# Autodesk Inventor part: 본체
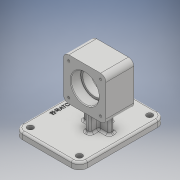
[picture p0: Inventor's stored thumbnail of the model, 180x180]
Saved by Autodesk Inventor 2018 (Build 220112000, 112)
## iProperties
Created: 2020-11
Part Number: 본체
Material: 일반
Document SubType Name: Modeling
Designer: USER
Density: 1 g/cm^3
Appearance: 기본값
Author: USER
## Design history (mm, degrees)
sketch "스케치1"
  geometry: L1 (-49, -65)-(49, -65); L2 (49, -65)-(49, 65); L3 (49, 65)-(-49, 65); L4 (-49, 65)-(-49, -65); L5 (-49, -65)-(49, 65); L6 (49, -65)-(-49, 65); 1 further point
  constraints: 12 end point, 2 midpoint, 2 parallel, 1 horizontal, 1 perpendicular
  dimensions: "d0" = 98 distance of L3.end L2.end; "d1" = 130 distance of L2.end L1.end
extrude "돌출1" new body sketch "스케치1" distance "d2" = 10; taper "d3" = 0 deg
fillet "모깎기1" dims "d4" = 12
fillet "모깎기2" dims "d5" = 3
sketch "스케치2"
  geometry: L1 (19, 38)-(-45, 38); L2 (-45, 38)-(-45, 102); L3 (-45, 102)-(19, 102); L4 (19, 102)-(19, 38); L5 (19, 38)-(-45, 102); L6 (-45, 38)-(19, 102); L7 (-13, 102)-(-13, 38); L8 (49, 7)-(49, 0) reference; L9 (19, 70)-(-45, 70); L10 (37, 0)-(-37, 0) reference; 2 further points
  constraints: 16 end point, 6 midpoint, 2 parallel, 1 horizontal, 1 perpendicular
  dimensions: "d6" = 64 distance of L2.end L3.end; "d7" = 64 distance of L1.end L2.end; "d8" = 62 distance between parallel lines of L8 L7; "d9" = 70 distance between parallel lines of L9 L10
extrude "돌출2" join sketch "스케치2" stored distance "d10" = 42; taper "d11" = 0 deg
fillet "모깎기3" dims "d12" = 8
sketch "스케치3"
  geometry: L1 (-7, 4)-(33, 4); L2 (33, 4)-(33, -4); L3 (33, -4)-(-7, -4); L4 (-7, -4)-(-7, 4); L5 (13, 4)-(13, -4); L6 (-7, 0)-(33, 0); L7 (-49, 53)-(-49, -53) reference; L8 (37, 65)-(-37, 65) reference; 1 further point
  constraints: 12 end point, 4 midpoint, 2 parallel, 1 horizontal, 1 perpendicular
  dimensions: "d13" = 62 distance between parallel lines of L7 L5; "d14" = 65 distance between parallel lines of L8 L6; "d15" = 8 distance of L3.end L1.start; "d16" = 40 distance of L1.start L1.end
extrude "돌출3" join sketch "스케치3" stored distance "d17" = 42; taper "d18" = 0 deg
sketch "스케치4"
  geometry: L1 (9, 17)-(17, 17); L2 (17, 17)-(17, -17); L3 (17, -17)-(9, -17); L4 (9, -17)-(9, 17); L5 (9, 0)-(17, 0); L6 (13, -17)-(13, 17); L7 (-49, 53)-(-49, -53) reference; L8 (37, 65)-(-37, 65) reference; 1 further point
  constraints: 12 end point, 4 midpoint, 2 parallel, 1 horizontal, 1 perpendicular
  dimensions: "d19" = 62 distance between parallel lines of L7 L6; "d20" = 65 distance between parallel lines of L8 L5; "d21" = 8 distance of L1.start L1.end; "d22" = 34 distance of L1.end L2.end
extrude "돌출4" join sketch "스케치4" stored distance "d23" = 42; taper "d24" = 0 deg
fillet "모깎기4" dims "d25" = 3
fillet "모깎기5" dims "d26" = 3
fillet "모깎기6" dims "d27" = 3
sketch "스케치5"
  geometry: L1 (37, 102)-(-11, 102) reference; L2 (-19, 94)-(-19, 46) reference; C1 r 21 at (13, 70); 3 further points
  constraints: 2 midpoint, 1 centre point, 1 horizontal alignment, 1 vertical alignment
  dimensions: "d28" = 42 diameter of C1
extrude "돌출5" cut sketch "스케치5" distance "d29" = 15; taper "d30" = 0 deg
sketch "스케치6"
  geometry: C1 r 21 at (0, 0) reference; C2 r 18 at (0, 0); 1 further point
  constraints: 1 centre point, 1 coincident
  dimensions: "d31" = 36 diameter of C2
extrude "돌출6" cut sketch "스케치6" extent not by distance; stored distance "d32" = 15; taper "d33" = 0 deg
fillet "모깎기7" dims "d34" = 0.3
fillet "모깎기8" dims "d35" = 0.3
chamfer "모따기1" distance "d36" = 1; stored, may be unused: second distance "d37" = 2, angle "d38" = 45 deg
chamfer "모따기2" distance "d39" = 1; stored, may be unused: second distance "d40" = 2, angle "d41" = 45 deg
sketch "스케치7"
  geometry: A1 r 8 centre (-11, 94) between (-11, 102) and (-19, 94) reference; A2 r 8 centre (-11, 46) between (-19, 46) and (-11, 38) reference; A3 r 8 centre (37, 46) between (37, 38) and (45, 46) reference; A4 r 8 centre (37, 94) between (45, 94) and (37, 102) reference; 5 further points
  constraints: 4 coincident
hole "구멍1" sketch "스케치7" at (-11, 94), (-11, 46), (37, 46), (37, 94) diameter "d42" = 3.242; stored, may be unused: countersink angle "d46" = 90 deg, drill point angle "d48" = 118 deg; dims "d43" = 8, "d44" = 4, "d45" = 2, "d47" = 10
sketch "스케치8"
  geometry: A1 r 12 centre (-37, 53) between (-37, 65) and (-49, 53) reference; A2 r 12 centre (-37, -53) between (-49, -53) and (-37, -65) reference; A3 r 12 centre (37, -53) between (37, -65) and (49, -53) reference; A4 r 12 centre (37, 53) between (49, 53) and (37, 65) reference; 5 further points
  constraints: 4 coincident
hole "구멍2" sketch "스케치8" at (-37, 53), (-37, -53), (37, -53), (37, 53) diameter "d49" = 9; stored, may be unused: countersink angle "d53" = 90 deg, drill point angle "d55" = 118 deg; dims "d50" = 8, "d51" = 4, "d52" = 2, "d54" = 10
sketch "스케치9"
  geometry: L1 (37, 65)-(-37, 65) reference; L2 (-49, 53)-(-49, -53) reference; 2 further points
  constraints: 1 other
  dimensions: "d56" = 65 distance from line of L1 point (-39, 0); "d57" = 10 distance from line of point (-39, 0) L2
feature "엠보싱1" sketch "스케치9" dims "d0" = 98, "d1" = 130, "d6" = 64, "d7" = 64, "d8" = 62, "d9" = 70, "d58" = 0.5, "d59" = 0
node "솔리드1"
mirror "미러1"
mirror "미러2"
